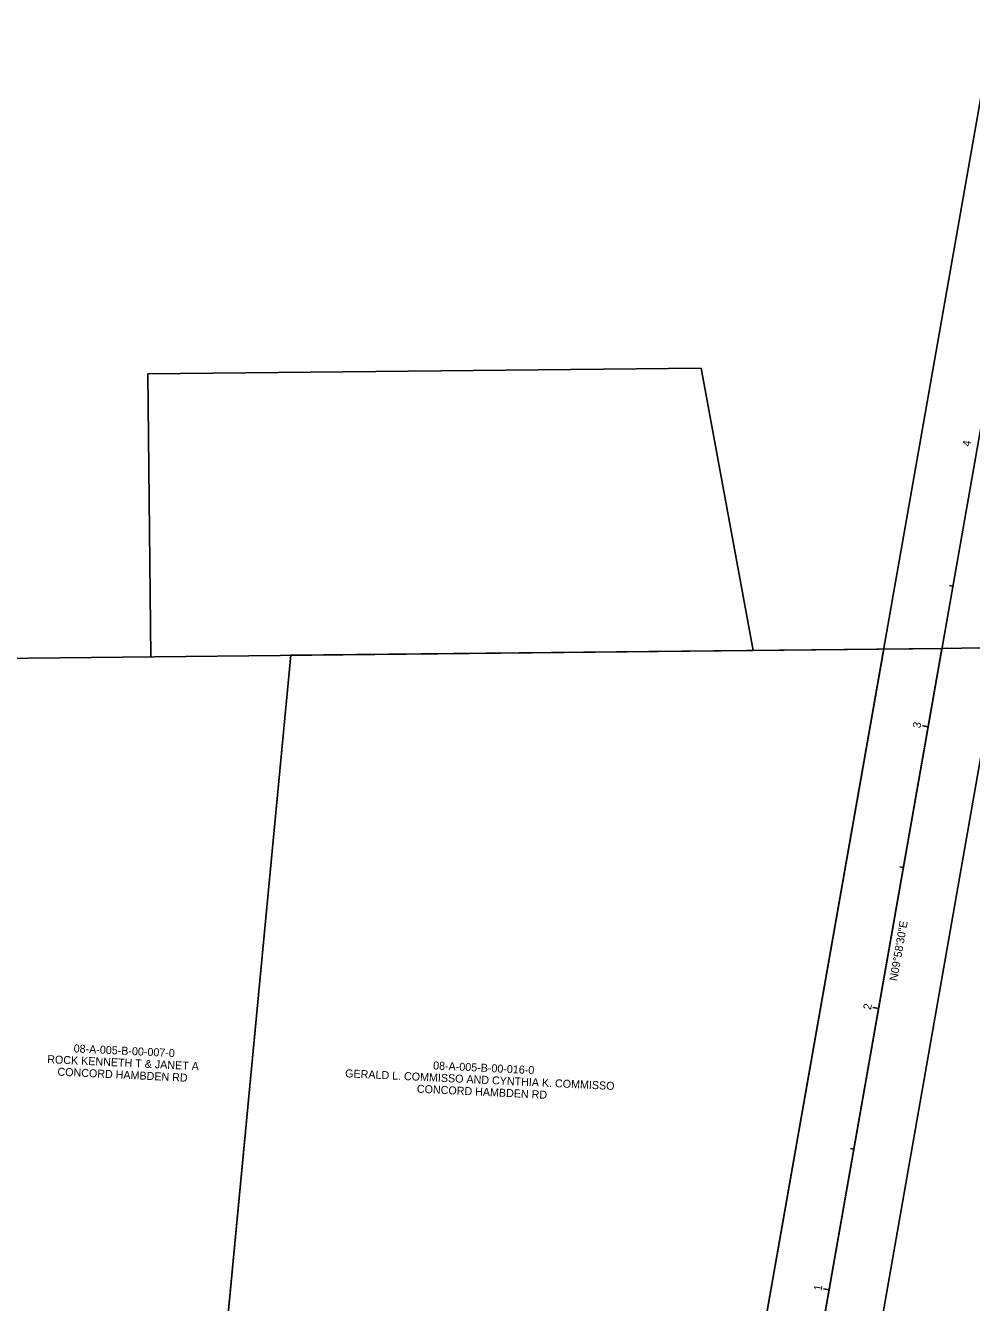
# Model space of a CAD drawing. Extents: x 2318731 to 2320621, y 732958 to 734198.
# Drawn here: x 2319138.4 to 2319469, y 733628.7 to 734075.3 of the extents above; entities that cross this region are included whole.
import ezdxf

# ---------------------------------------------------------------- set-up
doc = ezdxf.new("R2010")
doc.units = 0
for name, color, linetype in [('DV_X_Section_VMS_Line', 7, 'Continuous'), ('RW_X_CL_100_Bearings', 7, 'Continuous'), ('RW_X_CL_100_Stations', 7, 'Continuous'), ('RW_X_CL_500_Bearings', 7, 'Continuous'), ('RW_X_CL_500_Stations', 7, 'Continuous'), ('RW_X_Text', 7, 'Continuous'), ('SC_Scratch4', 7, 'Continuous'), ('SC_Scratch5', 7, 'Continuous'), ('V-SURV-IPF', 7, 'Continuous'), ('V-SURV-PARL-LINE', 7, 'Continuous'), ('V-SURV-RWAY', 7, 'Continuous')]:
    doc.layers.add(name, color=color, linetype=linetype)

msp = doc.modelspace()

# ---------------------------------------------------------------- linework, layer by layer
at = {"layer": 'DV_X_Section_VMS_Line'}
for p, q in [((2319458.71, 733857.41), (2320596.89, 733876.33)), ((2318730.61, 733849.8), (2319458.71, 733857.41))]:
    msp.add_line(p, q, dxfattribs=at)
at = {"layer": 'RW_X_CL_100_Stations'}
for p, q in [((2319462.56, 733879.27), (2319461.37, 733879.48)), ((2319453.89, 733830.03), (2319451.92, 733830.38)), ((2319445.23, 733780.79), (2319444.05, 733780.99)), ((2319436.57, 733731.54), (2319434.6, 733731.89)), ((2319427.91, 733682.3), (2319426.73, 733682.51)), ((2319419.25, 733633.05), (2319417.28, 733633.4))]:
    msp.add_line(p, q, dxfattribs=at)
at = {"layer": 'RW_X_CL_500_Stations'}
for p, q in [((2319453.89, 733830.03), (2319452.71, 733830.24)), ((2319436.57, 733731.54), (2319435.39, 733731.75)), ((2319419.25, 733633.05), (2319418.07, 733633.26))]:
    msp.add_line(p, q, dxfattribs=at)
at = {"layer": 'SC_Scratch4'}
msp.add_lwpolyline([(2319238.01, 733573.08), (2319387.15, 733565.99), (2319438.37, 733857.2), (2319458.71, 733857.41), (2319402.05, 733535.25), (2319235.88, 733543.15), (2319201.73, 733546.4), (2319204.58, 733576.26)], close=True, dxfattribs=at)
at = {"layer": 'SC_Scratch5'}
msp.add_lwpolyline([(2319402.05, 733535.25), (2319235.88, 733543.15), (2319201.73, 733546.4), (2319231.12, 733855.03), (2319458.71, 733857.41)], close=True, dxfattribs=at)
at = {"layer": 'V-SURV-IPF'}
for p, q in [((2319181.15, 733953.51), (2319374.52, 733955.53)), ((2319182.18, 733854.52), (2319181.15, 733953.51)), ((2319374.52, 733955.53), (2319392.71, 733856.72)), ((2319458.71, 733857.41), (2319886.73, 733864.52)), ((2319030.01, 733852.93), (2319458.71, 733857.41)), ((2319201.73, 733546.4), (2319231.13, 733855.14))]:
    msp.add_line(p, q, dxfattribs=at)
at = {"layer": 'V-SURV-PARL-LINE'}
for p, q in [((2319387.15, 733565.99), (2319476.73, 734075.32)), ((2319427.43, 733564.08), (2319479.14, 733858.08))]:
    msp.add_line(p, q, dxfattribs=at)
at = {"layer": 'V-SURV-RWAY'}
msp.add_line((2319401.93, 733534.57), (2319478.69, 733971.04), dxfattribs=at)

# ---------------------------------------------------------------- texts
at = {"layer": 'RW_X_CL_100_Bearings'}
msp.add_text('N09°58\'30"E', height=2.8, rotation=80.0249, dxfattribs=at).set_placement((2319443.1, 733740.96))
at = {"layer": 'RW_X_CL_100_Stations'}
for s, p in [('4', (2319468.57, 733927.9)), ('3', (2319451.2, 733829.4)), ('2', (2319433.92, 733730.89)), ('1', (2319416.63, 733632.56))]:
    msp.add_text(s, height=2.8, rotation=80.0249, dxfattribs=at).set_placement(p)
at = {"layer": 'RW_X_CL_500_Bearings'}
msp.add_text('N09°58\'30"E', height=2.8, rotation=80.0249, dxfattribs=at).set_placement((2319443.1, 733740.96))
at = {"layer": 'RW_X_Text'}
for s, p in [('ROCK KENNETH T & JANET A', (2319145.93, 733712.4)), ('08-A-005-B-00-007-0', (2319155.17, 733716.16)), ('CONCORD HAMBDEN RD', (2319149.49, 733708.02)), ('GERALD L. COMMISSO AND CYNTHIA K. COMMISSO', (2319250.07, 733707.45)), ('08-A-005-B-00-016-0', (2319280.82, 733710.19)), ('CONCORD HAMBDEN RD', (2319275.14, 733702.05))]:
    msp.add_text(s, height=2.8, rotation=357.2785, dxfattribs=at).set_placement(p)

doc.saveas('drawing.dxf')
